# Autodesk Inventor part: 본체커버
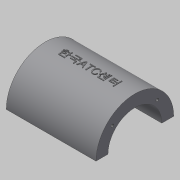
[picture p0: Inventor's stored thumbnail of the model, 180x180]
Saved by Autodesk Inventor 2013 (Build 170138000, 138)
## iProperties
Created: 2015-12
Part Number: 본체커버
Material: 일반
Document SubType Name: Modeling
Designer: mduedu
Density: 2.71 g/cm^3
Mass: 199.348 g
Surface Area: 200.806 cm^2
Volume: 73.5601 cm^3
Author: mduedu
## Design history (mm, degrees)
sketch "스케치1"
  geometry: L1 (45, 40)-(-45, 40); L2 (-45, 40)-(-45, -40); L3 (-45, -40)-(45, -40); L4 (45, -40)-(45, 40); L5 (45, 40)-(-45, -40); L6 (-45, 40)-(45, -40); 1 further point
  constraints: 12 end point, 2 midpoint, 2 parallel, 1 horizontal, 1 perpendicular
  dimensions: "d0" = 90 distance of L2.end L3.end; "d2" = 80 distance of L1.end L2.end
extrude "돌출1" new body sketch "스케치1" distance "d3" = 10; taper "d4" = 0 deg
sketch "스케치2"
  geometry: L1 (0, 40)-(0, -40) reference; C1 r 32.5 at (80, 0); 1 further point
  constraints: 1 centre point
  dimensions: "d5" = 65 diameter of C1; "d6" = 80 distance from line of C1.centre L1
extrude "돌출2" join sketch "스케치2" stored distance "d7" = 75; taper "d8" = 0 deg
sketch "스케치3"
  geometry: L1 (-27.5, -20)-(27.5, -20); L2 (27.5, -20)-(27.5, 20); L3 (27.5, 20)-(-27.5, 20); L4 (-27.5, 20)-(-27.5, -20); L5 (-27.5, -20)-(27.5, 20); L6 (27.5, -20)-(-27.5, 20); 1 further point
  constraints: 12 end point, 2 midpoint, 2 parallel, 1 horizontal, 1 perpendicular
  dimensions: "d9" = 55 distance of L2.end L3.end; "d11" = 40 distance of L1.end L2.end
extrude "돌출3" new body sketch "스케치3" stored distance "d12" = 75; taper "d13" = 0 deg
fillet "모깎기1"
fillet "모깎기2"
feature "결합1"
  node "솔리드2"
fillet "모깎기3" dims "d14" = 10
sketch "스케치4"
  geometry: L1 (-37.5, 47.5)-(37.5, 47.5) reference; L2 (35, 10)-(45, 10) reference; L3 (32.5, 47.5)-(40, 10); L4 (37.5, 47.5)-(37.5, 112.5) reference; L5 (45, 10)-(45, 0) reference; 1 further point
  constraints: 2 end point, 1 midpoint, 1 point on line
  dimensions: "d15" = 5 distance from line of L3.start L4; "d16" = 5 distance from line of L3.end L5
sketch "스케치5"
  geometry: L1 (10, 40)-(10, 30) reference; L2 (10, 35)-(56.569, 22.522); L3 (0, 40)-(10, 40) reference; 2 further points
  constraints: 2 end point, 1 midpoint, 2 other
  dimensions: "d17" = 5 distance from line of L2.start L3; "d18" = 15 deg angle of L2 L3
feature "리브1" dims "d19" = 1, "d20" = 6, "d21" = 0, "d22" = 0, "d23" = 1, "d24" = 1
feature "리브2" dims "d25" = 1, "d26" = 6, "d27" = 0, "d28" = 0, "d29" = 1, "d30" = 1
fillet "모깎기4" dims "d31" = 2
fillet "모깎기5" dims "d32" = 2
fillet "모깎기6" dims "d33" = 2
sketch "스케치6"
  geometry: A1 r 10 centre (-35, 30) between (-35, 40) and (-45, 30) reference; A2 r 10 centre (35, 30) between (45, 30) and (35, 40) reference; A3 r 10 centre (35, -30) between (35, -40) and (45, -30) reference; A4 r 10 centre (-35, -30) between (-45, -30) and (-35, -40) reference; 5 further points
  constraints: 4 coincident
hole "구멍1" sketch "스케치6" at (-35, 30), (35, 30), (35, -30), (-35, -30) diameter "d34" = 7; stored, may be unused: countersink angle "d38" = 90 deg, drill point angle "d40" = 118 deg; dims "d35" = 6, "d36" = 12, "d37" = 3, "d39" = 8
fillet "모깎기7" dims "d41" = 2
hole "구멍2" diameter "d44" = 45; stored, may be unused: countersink angle "d48" = 90 deg, drill point angle "d50" = 118 deg; dims "d42" = 10, "d43" = 10, "d45" = 6, "d46" = 4, "d47" = 2, "d49" = 8
sketch "스케치7" dims "d52" = 26.5
  geometry: L1 (0, 0)-(32.5, 0); L2 (0, 0)-(22.981, 22.981); A1 r 32.5 centre (0, 0) between (32.5, 0) and (22.981, 22.981) reference; 3 further points
  constraints: 4 end point, 2 point on circle, 1 coincident, 1 horizontal, 1 point on line, 3 other
  dimensions: "d51" = 45 deg angle of L2 L1
hole "구멍3" sketch "스케치7" at (18.738, 18.738) diameter "d54" = 2.459; stored, may be unused: countersink angle "d58" = 90 deg, drill point angle "d60" = 118 deg; dims "d55" = 8, "d56" = 4, "d57" = 2, "d59" = 10
sketch "스케치13"
  geometry: L1 (-45, 80)-(105, 80); L2 (105, 80)-(105, -30); L3 (105, -30)-(-45, -30); L4 (-45, -30)-(-45, 80); L5 (0, 0)-(60, 0) reference; C1 r 32.5 at (30, 80) reference; 1 further point
  constraints: 8 end point, 2 parallel, 1 coincident, 1 horizontal, 1 midpoint, 1 perpendicular
  dimensions: "d99" = 30 distance between parallel lines of L3 L5; "d126" = 150 distance between parallel lines of L2 L4
extrude "돌출8" cut sketch "스케치13" stored distance "d97" = 10; taper "d98" = 0 deg
node "작업 평면2"
sketch "스케치14"
  geometry: 2 further points
  constraints: 1 coincident, 1 other
feature "엠보싱1" sketch "스케치14" dims "d102" = 0.5, "d103" = 0
sketch "스케치18"
  geometry: L1 (0, -10)-(0, 0) reference; L2 (75, 0)-(75, -10) reference; L3 (0, -5)-(75, -5); C1 r 1.5 at (13, -5); 1 further point
  constraints: 2 end point, 2 midpoint, 1 centre point, 1 point on line
  dimensions: "d127" = 3 diameter of C1; "d128" = 13 distance from line of L1 C1.centre
extrude "돌출9" cut sketch "스케치18" distance "d129" = 2; taper "d130" = 0 deg
chamfer "모따기2" distance "d131" = 0.5; stored, may be unused: second distance "d132" = 2, angle "d133" = 45 deg
fillet "모깎기12" dims "d134" = 0.1
node "솔리드1"
mirror "대칭1"
mirror "대칭2"
pattern_circular "원형 패턴1" dims angle "d62" = 360 deg
mirror "대칭3"
mirror "대칭5"
mirror "대칭6"
